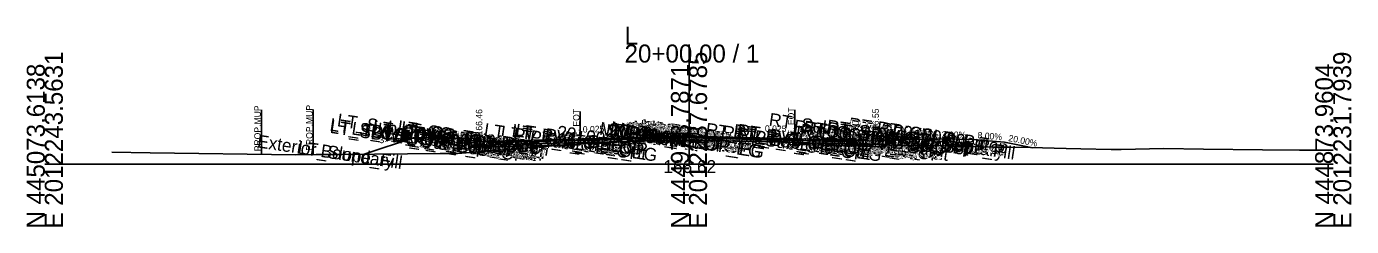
# Model space of a CAD drawing. Extents: x -26 to 4203, y -10 to 9526.
# Drawn here: x 997.2 to 1202.8, y -9.7 to 21.4 of the extents above; entities that cross this region are included whole.
import ezdxf

# ---------------------------------------------------------------- set-up
doc = ezdxf.new("R2010")
doc.units = 0
for name, color, linetype in [('Default', 7, 'Continuous'), ('Exist CMT Pavement', 7, 'Continuous'), ('Exist Cross Section Cell', 7, 'Continuous'), ('Exist XS Center Line Elevation Label', 7, 'Continuous'), ('Exist XS Ground Line', 7, 'Continuous'), ('Prop CMT Conc Surface', 7, 'Continuous'), ('Prop CMT Concrete Structures', 7, 'Continuous'), ('Prop CMT Pvmt Course 1', 7, 'Continuous'), ('Prop CMT Pvmt Course 1 CG', 7, 'Continuous'), ('Prop CMT Pvmt Course 1 Wedge', 7, 'Continuous'), ('Prop CMT Pvmt Course 2', 7, 'Continuous'), ('Prop CMT Pvmt Course 2 Wedge', 7, 'Continuous'), ('Prop CMT Pvmt Course 3', 7, 'Continuous'), ('Prop CMT Pvmt Course 3 Wedge', 7, 'Continuous'), ('Prop CMT Pvmt Surface', 7, 'Continuous'), ('Prop CMT Pvmt Wedge Surface 1', 7, 'Continuous'), ('Prop CMT Pvmt Wedge Surface 2', 7, 'Continuous'), ('Prop CMT Pvmt Wedge Surface 3', 7, 'Continuous'), ('Prop CMT Slope Grass', 7, 'Continuous'), ('Prop CMT Subgrade Earthwork', 7, 'Continuous'), ('Prop XS Hydro Elevations', 7, 'Continuous'), ('Prop XS Label Text', 7, 'Continuous'), ('Prop XS SE Text', 7, 'Continuous'), ('Prop XS Side Slope Text', 7, 'Continuous'), ('Scratch_Level_0', 7, 'Continuous')]:
    doc.layers.add(name, color=color, linetype=linetype)

msp = doc.modelspace()

# ---------------------------------------------------------------- linework, layer by layer
at = {"layer": 'Exist CMT Pavement'}
for points in [[(1100, 3.62), (1098.73, 3.64), (1097.07, 3.61), (1096.24, 3.6), (1094.49, 3.61), (1093.91, 3.61), (1093.84, 3.6), (1093.09, 3.57), (1091.22, 3.5), (1089.96, 3.46), (1088.72, 3.42), (1087.6, 3.35), (1086.2, 3.25), (1085.22, 3.22), (1083.72, 3.19), (1083.33, 3.17), (1083.11, 3.16)], [(1100, 3.62), (1100.6, 3.62), (1101.22, 3.61), (1103.24, 3.61), (1103.71, 3.61), (1104.42, 3.62), (1104.93, 3.63), (1105.63, 3.61), (1106.22, 3.6), (1108.57, 3.57), (1108.73, 3.57), (1111.15, 3.56), (1111.24, 3.56), (1113.59, 3.51), (1113.73, 3.51), (1113.89, 3.51), (1116.34, 3.42), (1116.45, 3.41), (1116.45, 3.41)]]:
    msp.add_lwpolyline(points, dxfattribs=at)
at = {"layer": 'Exist Cross Section Cell'}
for p, q in [((1100, 0), (1100, 18.58)), ((1000, 0), (1100, 0)), ((1100, 0), (1200, 0))]:
    msp.add_line(p, q, dxfattribs=at)
at = {"layer": 'Exist XS Ground Line'}
msp.add_lwpolyline([(1010.39, 1.88), (1016.36, 1.77), (1038.95, 1.47), (1042.13, 1.48), (1046.11, 1.5), (1061.38, 1.63), (1063.17, 1.65), (1064.07, 1.67), (1065.4, 1.77), (1081.29, 3.04), (1081.67, 3.06), (1082.55, 3.12), (1083.11, 3.16), (1083.72, 3.19), (1085.22, 3.22), (1086.2, 3.25), (1087.6, 3.35), (1088.72, 3.42), (1089.96, 3.46), (1091.22, 3.5), (1093.09, 3.57), (1093.91, 3.61), (1094.49, 3.61), (1096.24, 3.6), (1097.07, 3.61), (1098.73, 3.64), (1100, 3.62), (1100.6, 3.62), (1101.22, 3.61), (1103.24, 3.61), (1103.71, 3.61), (1104.42, 3.62), (1104.93, 3.63), (1105.63, 3.61), (1106.22, 3.6), (1108.73, 3.57), (1111.24, 3.56), (1113.89, 3.51), (1116.45, 3.41), (1117.18, 3.27), (1117.57, 3.21), (1118.84, 3.23), (1119.59, 3.3), (1120.71, 3.28), (1122.16, 3.26), (1122.48, 3.26), (1123.87, 3.23), (1125.57, 3.15), (1126.75, 3.09), (1129.83, 3), (1130.3, 3), (1133.45, 2.9), (1134.24, 2.89), (1136.2, 2.9), (1137.23, 2.87), (1139.25, 2.84), (1140.59, 2.8), (1142.62, 2.79), (1144.12, 2.73), (1147.12, 2.66), (1149.85, 2.63), (1152.99, 2.56), (1158.53, 2.42), (1160.8, 2.38), (1165.52, 2.28), (1166.61, 2.27), (1167.07, 2.27), (1173.73, 2.44), (1179.88, 2.3), (1189.02, 2.2), (1194.75, 2.17), (1198.16, 2.19), (1200, 2.19)], dxfattribs=at)
at = {"layer": 'Prop CMT Conc Surface'}
for points in [[(1067.41, 3.46), (1067.41, 3.96), (1066.91, 3.96)], [(1069.41, 3.59), (1067.41, 3.46)], [(1126.97, 3.68), (1128.97, 3.55)]]:
    msp.add_lwpolyline(points, dxfattribs=at)
at = {"layer": 'Prop CMT Concrete Structures'}
for p, q in [((1128.97, 3.55), (1129.47, 3.66)), ((1129.47, 3.66), (1133.47, 3.82)), ((1133.47, 3.82), (1138.97, 3.93)), ((1138.97, 3.93), (1143.97, 3.83)), ((1143.97, 3.83), (1148.97, 3.43)), ((1148.97, 3.43), (1153.37, 2.55))]:
    msp.add_line(p, q, dxfattribs=at)
for points in [[(1102, 4.31), (1101.99, 4.47), (1101.24, 4.72), (1098.08, 4.79), (1094.92, 4.63), (1094.17, 4.38), (1094.16, 4.21)], [(1094.16, 4.21), (1100, 4.36), (1102, 4.31)], [(1069.41, 3.59), (1067.41, 3.46), (1067.41, 3.96), (1066.91, 3.96)], [(1066.91, 3.96), (1066.91, 2.95), (1069.41, 3.01)], [(1069.41, 3.01), (1069.41, 3.59)], [(1126.97, 3.1), (1126.97, 3.68)], [(1126.97, 3.68), (1128.97, 3.55)], [(1129.47, 3.66), (1129.47, 3.04), (1126.97, 3.1)]]:
    msp.add_lwpolyline(points, dxfattribs=at)
at = {"layer": 'Prop CMT Pvmt Course 1'}
for points in [[(1100, 4.36), (1069.41, 3.59)], [(1083.11, 3.81), (1100, 4.23)], [(1100, 4.11), (1100, 4.36)], [(1100, 4.36), (1126.97, 3.68)], [(1100, 4.11), (1100, 4.36)], [(1100, 4.23), (1100, 4.11), (1100, 4.11)], [(1116.45, 3.82), (1100, 4.23)], [(1100, 4.23), (1100, 4.11), (1100, 4.11)], [(1069.41, 3.34), (1083.11, 3.68)], [(1069.41, 3.59), (1069.41, 3.34)], [(1083.11, 3.68), (1083.11, 3.81)], [(1116.45, 3.69), (1116.45, 3.82)], [(1126.97, 3.43), (1117.57, 3.67)], [(1126.97, 3.68), (1126.97, 3.43)]]:
    msp.add_lwpolyline(points, dxfattribs=at)
at = {"layer": 'Prop CMT Pvmt Course 1 CG'}
for points in [[(1069.41, 3.01), (1066.41, 2.93), (1066.07, 2.59)], [(1066.07, 2.59), (1069.41, 2.68)], [(1069.41, 2.68), (1069.41, 3.01)], [(1126.97, 3.1), (1129.97, 3.02), (1130.31, 2.68)], [(1126.97, 2.77), (1126.97, 3.1)], [(1130.31, 2.68), (1126.97, 2.77)]]:
    msp.add_lwpolyline(points, dxfattribs=at)
at = {"layer": 'Prop CMT Pvmt Course 1 Wedge'}
for points in [[(1083.11, 3.81), (1083.33, 3.81), (1083.72, 3.82), (1085.22, 3.86), (1086.2, 3.89), (1087.6, 3.92), (1088.72, 3.95), (1089.96, 3.98), (1091.22, 4.01), (1093.09, 4.06), (1093.84, 4.08), (1093.91, 4.08), (1094.49, 4.09), (1096.24, 4.14), (1097.07, 4.16), (1098.73, 4.2), (1100, 4.23)], [(1100, 4.23), (1100, 4.11)], [(1100, 4.11), (1100, 4.23)], [(1100, 4.23), (1100.6, 4.22), (1101.22, 4.2), (1103.24, 4.15), (1103.71, 4.14), (1104.42, 4.12), (1104.93, 4.11), (1105.63, 4.09), (1106.22, 4.08), (1108.57, 4.02), (1108.73, 4.01), (1111.15, 3.95), (1111.24, 3.95), (1113.59, 3.89), (1113.73, 3.89), (1113.89, 3.88), (1116.25, 3.82), (1116.34, 3.82), (1116.45, 3.82)], [(1100, 4.11), (1098.73, 4.07), (1097.07, 4.03), (1096.24, 4.01), (1094.49, 3.97), (1093.91, 3.95), (1093.84, 3.95), (1093.09, 3.93), (1091.22, 3.89), (1089.96, 3.86), (1088.72, 3.82), (1087.6, 3.8), (1086.2, 3.76), (1085.22, 3.74), (1083.72, 3.7), (1083.33, 3.69), (1083.11, 3.68)], [(1083.11, 3.68), (1083.11, 3.81)], [(1116.45, 3.69), (1116.25, 3.7), (1113.89, 3.76), (1113.73, 3.76), (1113.59, 3.77), (1111.24, 3.82), (1111.15, 3.83), (1108.73, 3.89), (1108.57, 3.89), (1106.22, 3.95), (1105.63, 3.97), (1104.93, 3.98), (1104.42, 4), (1103.71, 4.01), (1103.24, 4.03), (1101.22, 4.08), (1100.6, 4.09), (1100, 4.11)], [(1116.45, 3.82), (1116.45, 3.69)]]:
    msp.add_lwpolyline(points, dxfattribs=at)
at = {"layer": 'Prop CMT Pvmt Course 2'}
for points in [[(1083.11, 3.68), (1069.41, 3.34)], [(1069.41, 3.01), (1083.11, 3.35)], [(1069.41, 3.34), (1069.41, 3.01)], [(1083.11, 3.35), (1083.11, 3.68)], [(1116.45, 3.36), (1116.45, 3.69)], [(1117.57, 3.67), (1126.97, 3.43)], [(1126.97, 3.1), (1117.57, 3.33)], [(1126.97, 3.43), (1126.97, 3.1)]]:
    msp.add_lwpolyline(points, dxfattribs=at)
at = {"layer": 'Prop CMT Pvmt Course 2 Wedge'}
for points in [[(1083.11, 3.68), (1083.33, 3.69), (1083.72, 3.7), (1085.22, 3.74), (1086.2, 3.76), (1087.6, 3.8), (1088.72, 3.82), (1089.96, 3.86), (1091.22, 3.89), (1093.09, 3.93), (1093.84, 3.95), (1093.91, 3.95), (1094.49, 3.97), (1096.24, 4.01), (1097.07, 4.03), (1098.73, 4.07), (1100, 4.11)], [(1100, 3.77), (1098.73, 3.74), (1097.07, 3.7), (1096.24, 3.68), (1094.49, 3.63), (1093.91, 3.62), (1093.84, 3.62), (1093.09, 3.6), (1091.22, 3.55), (1089.96, 3.52), (1088.72, 3.49), (1087.6, 3.46), (1086.2, 3.43), (1085.22, 3.4), (1083.72, 3.37), (1083.33, 3.36), (1083.11, 3.35)], [(1083.11, 3.35), (1083.11, 3.68)], [(1100, 4.11), (1100.6, 4.09), (1101.22, 4.08), (1103.24, 4.03), (1103.71, 4.01), (1104.42, 4), (1104.93, 3.98), (1105.63, 3.97), (1106.22, 3.95), (1108.57, 3.89), (1108.73, 3.89), (1111.15, 3.83), (1111.24, 3.82), (1113.59, 3.77), (1113.73, 3.76), (1113.89, 3.76), (1116.25, 3.7), (1116.34, 3.7), (1116.45, 3.69), (1117.02, 3.68), (1117.18, 3.68), (1117.57, 3.67)], [(1100, 3.77), (1100, 4.11)], [(1100, 4.11), (1100, 3.77)], [(1116.45, 3.41), (1116.45, 3.41), (1116.34, 3.42), (1113.89, 3.51), (1113.73, 3.51), (1113.59, 3.51), (1111.24, 3.56), (1111.15, 3.56), (1108.73, 3.57), (1108.57, 3.57), (1107.45, 3.59), (1106.22, 3.62), (1105.63, 3.63), (1104.93, 3.65), (1104.42, 3.66), (1103.71, 3.68), (1103.24, 3.69), (1101.22, 3.74), (1100.6, 3.76), (1100, 3.77)], [(1116.45, 3.69), (1116.45, 3.36)]]:
    msp.add_lwpolyline(points, dxfattribs=at)
at = {"layer": 'Prop CMT Pvmt Course 3'}
for points in [[(1083.11, 3.35), (1069.41, 3.01)], [(1069.41, 2.68), (1083.11, 3.02)], [(1069.41, 3.01), (1069.41, 2.68)], [(1083.11, 3.02), (1083.11, 3.35)], [(1116.45, 3.03), (1116.45, 3.36)], [(1126.97, 2.77), (1116.45, 3.03)], [(1117.57, 3.33), (1126.97, 3.1)], [(1126.97, 3.1), (1126.97, 2.77)]]:
    msp.add_lwpolyline(points, dxfattribs=at)
at = {"layer": 'Prop CMT Pvmt Course 3 Wedge'}
for points in [[(1083.11, 3.35), (1083.33, 3.36), (1083.72, 3.37), (1085.22, 3.4), (1086.2, 3.43), (1087.6, 3.46), (1088.72, 3.49), (1089.96, 3.52), (1091.22, 3.55), (1093.09, 3.6), (1093.84, 3.62), (1093.91, 3.62), (1094.49, 3.64), (1096.24, 3.68), (1097.07, 3.7), (1098.73, 3.74), (1100, 3.77)], [(1100, 3.62), (1098.73, 3.64), (1097.07, 3.61), (1096.24, 3.6), (1094.49, 3.61), (1093.91, 3.61), (1093.84, 3.6), (1093.09, 3.57), (1091.22, 3.5), (1089.96, 3.46), (1088.72, 3.42), (1087.6, 3.35), (1086.2, 3.25), (1085.22, 3.22), (1083.72, 3.19), (1083.33, 3.17), (1083.11, 3.16)], [(1083.11, 3.16), (1083.11, 3.35)], [(1100, 3.77), (1100.6, 3.76), (1101.22, 3.74), (1103.24, 3.69), (1103.71, 3.68), (1104.42, 3.66), (1104.93, 3.65), (1105.63, 3.63), (1106.22, 3.62), (1107.48, 3.59)], [(1100, 3.62), (1100, 3.77)], [(1100, 3.77), (1100, 3.62)], [(1107.48, 3.59), (1106.22, 3.6), (1105.63, 3.61), (1104.93, 3.63), (1104.42, 3.62), (1103.71, 3.61), (1103.24, 3.61), (1101.22, 3.61), (1100.6, 3.62), (1100, 3.62)], [(1116.45, 3.36), (1116.45, 3.24)], [(1117.57, 3.21), (1117.18, 3.27), (1117.02, 3.3), (1116.73, 3.35)], [(1116.73, 3.35), (1117.02, 3.35)], [(1117.02, 3.35), (1117.18, 3.34), (1117.57, 3.33)]]:
    msp.add_lwpolyline(points, dxfattribs=at)
at = {"layer": 'Prop CMT Pvmt Surface'}
for points in [[(1100, 4.36), (1069.41, 3.59)], [(1100, 4.36), (1126.97, 3.68)]]:
    msp.add_lwpolyline(points, dxfattribs=at)
at = {"layer": 'Prop CMT Pvmt Wedge Surface 1'}
for points in [[(1100, 4.23), (1083.11, 3.81)], [(1100, 4.23), (1116.45, 3.82)], [(1083.11, 3.68), (1069.41, 3.34)], [(1069.41, 3.34), (1069.41, 3.59)], [(1083.11, 3.81), (1083.11, 3.68)], [(1116.45, 3.82), (1116.45, 3.69)], [(1117.57, 3.67), (1126.97, 3.43)]]:
    msp.add_lwpolyline(points, dxfattribs=at)
at = {"layer": 'Prop CMT Pvmt Wedge Surface 2'}
for points in [[(1100, 4.11), (1069.41, 3.34)], [(1069.41, 3.34), (1069.41, 3.59)], [(1100, 4.11), (1126.97, 3.43)]]:
    msp.add_lwpolyline(points, dxfattribs=at)
at = {"layer": 'Prop CMT Pvmt Wedge Surface 3'}
for points in [[(1100, 3.77), (1069.41, 3.01)], [(1069.41, 3.01), (1069.41, 3.59)], [(1100, 3.77), (1126.97, 3.1)]]:
    msp.add_lwpolyline(points, dxfattribs=at)
at = {"layer": 'Prop CMT Slope Grass'}
msp.add_lwpolyline([(1066.91, 3.96), (1057.41, 4.15), (1049.55, 1.53)], dxfattribs=at)
at = {"layer": 'Prop CMT Subgrade Earthwork'}
for points in [[(1069.41, 2.68), (1066.07, 2.59), (1064.65, 4.01)], [(1083.11, 3.02), (1069.41, 2.68)], [(1083.11, 3.02), (1083.11, 3.16)], [(1116.45, 3.03), (1116.45, 3.41)], [(1116.45, 3.03), (1126.97, 2.77)], [(1126.97, 2.77), (1130.31, 2.68), (1131.37, 3.74)], [(1126.97, 2.77), (1126.97, 2.77)]]:
    msp.add_lwpolyline(points, dxfattribs=at)
at = {"layer": 'Prop XS Label Text'}
for p, q in [((1033.62, 8.42), (1033.62, 1.42)), ((1041.67, 8.5), (1041.67, 1.5)), ((1116.45, 8.41), (1116.45, 3.41)), ((1083.11, 8.16), (1083.11, 3.16))]:
    msp.add_line(p, q, dxfattribs=at)

# ---------------------------------------------------------------- texts
at = {"layer": 'Default'}
msp.add_text('-', height=0.0001, dxfattribs=at).set_placement((1000, 0))
at = {"layer": 'Exist Cross Section Cell'}
for s, p in [('L', (1090, 18.58)), ('20+00.00 / 1', (1090, 15.78))]:
    msp.add_text(s, height=2.8, dxfattribs=at).set_placement(p)
for s, p in [('E 2012243.5631', (1002.8, -10)), ('E 2012237.6785', (1102.8, -10)), ('E 2012231.7939', (1202.8, -10)), ('N 445073.6138', (1000, -10)), ('N 444973.7871', (1100, -10)), ('N 444873.9604', (1200, -10))]:
    msp.add_text(s, height=2.8, rotation=90, dxfattribs=at).set_placement(p)
at = {"layer": 'Exist XS Center Line Elevation Label'}
msp.add_text('166.62', height=2, dxfattribs=at).set_placement((1096.03, -1.38))
at = {"layer": 'Prop XS Hydro Elevations'}
for s, p in [('166.46', (1067.91, 4.46)), ('166.55', (1129.47, 4.55))]:
    msp.add_text(s, height=1, rotation=90, dxfattribs=at).set_placement(p)
at = {"layer": 'Prop XS Label Text'}
for s, p in [('PROP.MUP', (1033.52, 1.99)), ('PROP.MUP', (1041.57, 2.07)), ('E. EOT', (1083.01, 4.19)), ('E. EOT', (1116.35, 4.43))]:
    msp.add_text(s, height=1, rotation=90, dxfattribs=at).set_placement(p)
at = {"layer": 'Prop XS SE Text'}
for s, rotation, p in [('0.025', 1.4307, (1083.52, 4.9)), ('0.025', 358.5682, (1111.77, 5.06)), ('4.00%', 2.2906, (1129.65, 3.99)), ('2.00%', 1.1458, (1134.41, 4.03)), ('2.00%', 358.8542, (1139.22, 4.1)), ('8.00%', 355.4261, (1144.76, 4.01)), ('20.00%', 348.6901, (1149.52, 3.6))]:
    msp.add_text(s, height=1, rotation=rotation, dxfattribs=at).set_placement(p)
at = {"layer": 'Prop XS Side Slope Text'}
msp.add_text('3:1', height=1, rotation=18.4386, dxfattribs=at).set_placement((1052.06, 3.16))
at = {"layer": 'Scratch_Level_0'}
for s, p in [('LT_SDWK_Out_Top', (1044.15, 5.2)), ('LT_SDWK_Out_Bot', (1044.18, 4.87)), ('LT_Sub_Trench_Out_DLT', (1045.29, 5.9)), ('LT_CSLP_Pnt', (1047.54, 4.62)), ('LT_SDWK_In_Top', (1050.76, 4.86)), ('LT_SDWK_In_Bot', (1050.79, 4.53)), ('LT_CG_Top_Face', (1054.66, 4.86)), ('LT_CG_Top_BOC', (1055.17, 4.71)), ('LT_PV_Sub_Tie_Out', (1068.09, 4.41)), ('LT_PV2_OEEOP', (1072.39, 4.28)), ('LT_PV1_OEEOP', (1072.95, 4.32)), ('MI_Face In', (1086, 4.59)), ('MI_Bot In', (1086.97, 4.28)), ('20+00.00', (1087.18, 4.3)), ('20+00.00', (1087.55, 4.53)), ('MI_Top In', (1087.7, 4.7)), ('RT_PV_IEEOP_EG', (1088.12, 4.39)), ('LT_PV_IEEOP_EG', (1088.17, 4.39)), ('RT_PV2_IEEOP', (1089.87, 4.61)), ('RT_PV3_IEEOP', (1089.87, 4.28)), ('LT_PV2_IEEOP', (1089.92, 4.61)), ('LT_PV3_IEEOP', (1089.92, 4.27)), ('RT_PV1_IEEOP', (1090.43, 4.66)), ('LT_PV1_IEEOP', (1090.48, 4.65)), ('MI_Crown', (1091.08, 4.82)), ('MI_Face Out', (1092.22, 4.93)), ('MI_Top Out', (1092.42, 5.04)), ('20+00.00', (1092.75, 4.79)), ('MI_Bot Out', (1093.21, 4.61)), ('20+00.00', (1094.64, 4.63)), ('20+00.00', (1095.01, 4.38)), ('RT_PV_Sub_Tie_Out', (1102.47, 4.47)), ('RT_PV2_OEEOP', (1106.8, 4.27)), ('RT_PV1_OEEOP', (1107.36, 4.31)), ('RT_Sub_Trench_Out_DLT', (1112.31, 6)), ('RT_CG_Top_Face', (1116.17, 4.96)), ('RT_CG_Top_Gut', (1117.14, 4.32)), ('RT_CG_Top_BOC', (1117.68, 4.81)), ('RT_SDWK_In_Top', (1121.27, 4.96)), ('RT_SDWK_In_Bot', (1121.3, 4.62)), ('RT_SDWK_Out_Top', (1124.66, 5.3)), ('RT_SDWK_Out_Bot', (1124.69, 4.96)), ('RT_CSLP_Pnt', (1129.05, 4.72)), ('20+00.00', (1131.6, 4.28)), ('Exterior Boundary', (1032.87, 2.61)), ('20+00.00', (1050.61, 4.19)), ('LT_CG1_Shelf_Out', (1052.96, 3.94)), ('LT_CG_Bot_BOC', (1055.21, 3.69)), ('LT_CG_Top_Gut', (1055.63, 4.22)), ('20+00.00', (1056.15, 4.08)), ('LT_Sub_OEOP', (1056.14, 3.07)), ('LT_CG_Bot_IE', (1059.29, 3.52)), ('LT_Sub_OEOT', (1059.45, 3.16)), ('LT_PV2_OEOT', (1059.54, 3.81)), ('LT_PV3_OEOT', (1059.54, 3.48)), ('20+00.00', (1060.14, 4)), ('LT_PV1_OEOT', (1060.1, 3.98)), ('20+00.00', (1061.24, 3.55)), ('LT_PV_OEEOP_EG', (1070.65, 4.02)), ('LT_Sub_OEEOP', (1072.3, 3.63)), ('LT_PV3_OEEOP', (1072.39, 3.95)), ('20+00.00', (1079.39, 4.05)), ('PV2_PGL', (1093.82, 4.02)), ('PV1_PGL', (1094.39, 4.19)), ('MI_Bot', (1095.09, 4.08)), ('RT_PV_OEEOP_EG', (1105.05, 4.08)), ('RT_Sub_OEEOP', (1106.7, 3.62)), ('RT_PV3_OEEOP', (1106.8, 3.94)), ('RT_CG1_Shelf_Out', (1116.47, 4.04)), ('RT_CG_Bot_IE', (1116.8, 3.61)), ('RT_Sub_OEOT', (1116.96, 3.26)), ('RT_PV2_OEOT', (1117.05, 3.91)), ('RT_PV3_OEOT', (1117.05, 3.57)), ('RT_PV1_OEOT', (1117.61, 4.07)), ('RT_CG_Bot_BOC', (1117.71, 3.79)), ('RT_Sub_OEOP', (1120.33, 3.17)), ('20+00.00', (1121.82, 3.6)), ('20+00.00', (1121.98, 3.82)), ('20+00.00', (1126.18, 4.17)), ('Exterior Boundary', (1127.59, 4.12)), ('20+00.00', (1127.79, 4.2)), ('RT_Slope_Fill', (1133.85, 3.18)), ('20+00.00', (1134.55, 3.42)), ('LT_Slope_Fill', (1039.17, 1.66))]:
    msp.add_text(s, height=2, rotation=351.4697, dxfattribs=at).set_placement(p)

doc.saveas('drawing.dxf')
